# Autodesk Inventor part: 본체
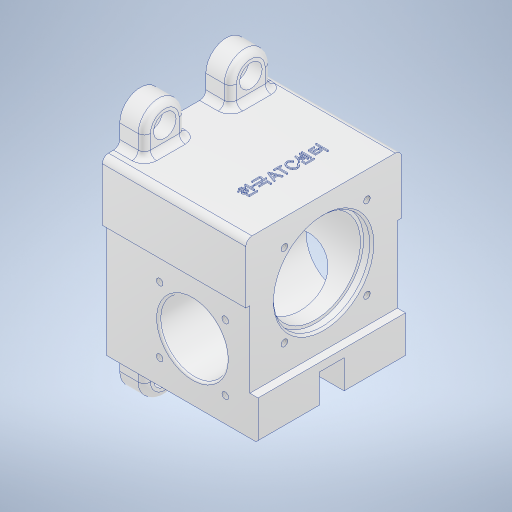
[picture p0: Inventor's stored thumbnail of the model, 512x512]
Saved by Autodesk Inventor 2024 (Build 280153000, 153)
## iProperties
Created: 2024-11
Part Number: 본체
Material: 알루미늄 6061
Document SubType Name: Modeling
Designer: user
Density: 2.7 g/cm^3
Appearance: 알루미늄 - 평지
Mass: 820.853 g
Surface Area: 546.228 cm^2
Volume: 304.02 cm^3
Author: user
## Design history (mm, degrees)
sketch "스케치1"
  geometry: L1 (-37, 0)-(37, 0); L2 (-37, 0)-(-37, 85); L3 (-37, 85)-(33, 85); L4 (33, 85)-(33, 19); L5 (33, 19)-(37, 19); L6 (37, 19)-(37, 0); L7 (-37, 56)-(33, 56); 2 further points
  constraints: 14 end point, 3 horizontal, 2 point on line, 1 coincident, 1 midpoint, 1 parallel, 1 perpendicular, 1 vertical
  dimensions: "d0" = 74 distance of L1.start L1.end; "d5" = 85 distance of L1.start L2.end; "d7" = 70 distance of L2.end L3.end; "d8" = 66 distance of L3.end L4.end; "d9" = 4 distance of L4.end L5.end; "d10" = 56 distance between parallel lines of L1 L7
extrude "돌출1" new body sketch "스케치1" stored distance "d11" = 72; taper "d12" = 0 deg
extrude "돌출2" join sketch "스케치1" stored distance "d13" = 76; taper "d14" = 0 deg
sketch "스케치2"
  geometry: L1 (-37, 56)-(-37, 0) reference; L2 (33, 85)-(-37, 85) reference; C1 r 16.5 at (5, 28); 1 further point
  constraints: 1 centre point
  dimensions: "d15" = 33 diameter of C1; "d16" = 57 distance from line of L2 C1.centre; "d17" = 42 distance from line of C1.centre L1
extrude "돌출3" cut sketch "스케치2" distance "d18" = 76; taper "d19" = 0 deg
fillet "모깎기1" dims "d20" = 1
sketch "스케치3"
  geometry: C1 r 17.5 at (5, 28) reference; 5 further points
  constraints: 2 horizontal alignment, 2 vertical alignment
  dimensions: "d21" = 32 distance of point (21, 12) point (-11, 12); "d22" = 16 horizontal distance of C1.centre point (21, 12); "d23" = 32 distance of point (-11, 12) point (-11, 44); "d24" = 16 horizontal distance of C1.centre point (-11, 12)
hole "구멍1" sketch "스케치3" at (-11, 44), (21, 44), (21, 12), (-11, 12) diameter "d25" = 3.242; stored, may be unused: countersink angle "d29" = 90 deg, drill point angle "d31" = 118 deg; dims "d26" = 8, "d27" = 4, "d28" = 2, "d30" = 10
sketch "스케치4"
  geometry: L1 (0, 0)-(72, 0) reference; L2 (30, 15)-(42, 15); L3 (42, 15)-(42, 0); L4 (42, 0)-(30, 0); L5 (30, 0)-(30, 15); 3 further points
  constraints: 8 end point, 2 midpoint, 2 parallel, 1 horizontal, 1 perpendicular, 1 point on line
  dimensions: "d32" = 12 distance of L3.end L4.end; "d33" = 15 distance of L2.end L3.end
extrude "돌출4" cut sketch "스케치4" extent not by distance; stored distance "d34" = 0; taper "d35" = 0 deg
sketch "스케치5"
  geometry: L1 (-30, 0)-(0, 0) reference; L2 (2, 85)-(-74, 85) reference; L3 (-72, 0)-(-42, 0) reference; L4 (-68.5, 95)-(-68.5, 85); L5 (-48.5, 95)-(-48.5, 85); L6 (-6.5, 95)-(-6.5, 85); L7 (-26.5, 95)-(-26.5, 85); L8 (-68.5, -10)-(-68.5, 0); L9 (-48.5, -10)-(-48.5, 0); L10 (-26.5, -10)-(-26.5, 0); L11 (-6.5, -10)-(-6.5, 0); A1 r 10 centre (-58.5, 95) between (-48.5, 95) and (-68.5, 95); A2 r 10 centre (-16.5, 95) between (-6.5, 95) and (-26.5, 95); A3 r 10 centre (-58.5, -10) between (-68.5, -10) and (-48.5, -10); A4 r 10 centre (-16.5, -10) between (-26.5, -10) and (-6.5, -10); 3 further points
  constraints: 16 end point, 10 point on circle, 8 point on line, 6 perpendicular, 4 centre point, 4 tangent, 1 parallel, 1 vertical
  dimensions: "d37" = 20 diameter of A1; "d38" = 10 vertical distance of A1.centre L2.end; "d39" = 20 diameter of A2; "d40" = 10 distance from line of A2.centre L2; "d41" = 42 distance of A2.centre A1.centre; "d42" = 20 diameter of A3; "d43" = 20 diameter of A4; "d44" = 42 distance of A4.centre A3.centre; "d45" = 10 distance from line of A3.centre L3; "d46" = 10 distance from line of L1 A4.centre; "d47" = 125 distance of point (-58.5, -20) point (-58.5, 105); "d48" = 22 distance of L7.end L5.end; "d49" = 6.5 dimension on L2.end L4.end; "d50" = 7.5 dimension on L2.start L6.end; "d51" = 5.5 dimension on L3.start L8.end; "d52" = 22 distance of L10.end L9.end
extrude "돌출5" join sketch "스케치5" distance "d53" = 12; taper "d54" = 0 deg
sketch "스케치6"
  geometry: A1 r 10 centre (16.5, 95) between (26.5, 95) and (6.5, 95) reference; A2 r 10 centre (58.5, 95) between (68.5, 95) and (48.5, 95) reference; A3 r 10 centre (16.5, -10) between (6.5, -10) and (26.5, -10) reference; A4 r 10 centre (58.5, -10) between (48.5, -10) and (68.5, -10) reference; 5 further points
  constraints: 4 coincident
hole "구멍2" sketch "스케치6" at (16.5, 95), (58.5, 95), (58.5, -10), (16.5, -10) diameter "d55" = 6.6; stored, may be unused: countersink angle "d59" = 90 deg, drill point angle "d61" = 118 deg; dims "d56" = 8, "d57" = 11, "d58" = 6.6, "d60" = 6.6
sketch "스케치7"
  geometry: L1 (74, 66)-(-2, 66) reference; C1 r 23.5 at (36, 33); 2 further points
  constraints: 1 centre point, 1 midpoint, 1 vertical alignment
  dimensions: "d62" = 47 diameter of C1; "d63" = 33 distance of point (36, 66) C1.centre
extrude "돌출6" cut sketch "스케치7" distance "d64" = 4; taper "d65" = 0 deg
sketch "스케치8"
  geometry: C1 r 23.5 at (0, 0) reference; C2 r 22 at (0, 0); 1 further point
  constraints: 1 centre point, 1 coincident
  dimensions: "d66" = 44 diameter of C2
extrude "돌출7" cut sketch "스케치8" distance "d67" = 48; taper "d68" = 0 deg
sketch "스케치9"
  geometry: C1 r 22 at (0, 0) reference; C2 r 17.5 at (0, 0); 1 further point
  constraints: 1 centre point, 1 coincident
  dimensions: "d69" = 35 diameter of C2
extrude "돌출8" cut sketch "스케치9" distance "d70" = 11; taper "d71" = 0 deg
sketch "스케치10"
  geometry: C1 r 17.5 at (0, 0) reference; C2 r 15 at (0, 0); 1 further point
  constraints: 1 centre point, 1 coincident
  dimensions: "d72" = 30 diameter of C2
extrude "돌출9" join sketch "스케치10" distance "d73" = 3; taper "d74" = 0 deg
chamfer "모따기1" distance "d75" = 1; stored, may be unused: second distance "d76" = 2, angle "d77" = 45 deg
fillet "모깎기2" dims "d78" = 0.6
fillet "모깎기3" dims "d79" = 3
sketch "스케치11"
  geometry: L1 (8.5, 33)-(65.5, 33); L2 (16.847, 53.153)-(57.153, 12.847); L3 (16.847, 12.847)-(57.153, 53.153); C1 r 15 at (37, 33) reference; A1 r 28.5 centre (37, 33) between (57.153, 53.153) and (57.153, 12.847); 3 further points
  constraints: 6 end point, 6 point on circle, 4 midpoint, 1 centre point, 1 coincident, 1 horizontal, 1 horizontal alignment
  dimensions: "d80" = 57 diameter of A1; "d81" = 45 deg angle of L1 L2; "d82" = 45 deg angle of L1 L3
hole "구멍3" sketch "스케치11" at (57.153, 53.153), (57.153, 12.847), (16.847, 12.847), (16.847, 53.153) diameter "d83" = 3.242; stored, may be unused: countersink angle "d87" = 90 deg, drill point angle "d89" = 118 deg; dims "d84" = 8, "d85" = 11, "d86" = 6.6, "d88" = 10
sketch "스케치13"
  geometry: L1 (70, 76)-(70, 0) reference; 2 further points
  constraints: 1 horizontal alignment, 1 other
  dimensions: "d93" = 20 distance from line of L1 point (50, 38)
feature "엠보싱2" sketch "스케치13" dims "d0" = 74, "d5" = 85, "d7" = 70, "d8" = 66, "d9" = 4, "d10" = 56, "d94" = 0.5, "d95" = 0
fillet "모깎기4" dims "d96" = 3
fillet "모깎기5" dims "d97" = 3
chamfer "모따기2" distance "d98" = 1; stored, may be unused: second distance "d99" = 2, angle "d100" = 45 deg
chamfer "모따기3" distance "d101" = 1; stored, may be unused: second distance "d102" = 2, angle "d103" = 45 deg
sketch "스케치14"
  geometry: L1 (74, 12)-(74, 0) reference; 4 further points
  constraints: 2 horizontal alignment, 1 midpoint
  dimensions: "d104" = 12 distance of point (62, 6) point (74, 6); "d105" = 40 distance of point (22, 6) point (62, 6)
hole "구멍4" sketch "스케치14" at (62, 6), (22, 6) diameter "d106" = 3.242; stored, may be unused: countersink angle "d110" = 90 deg, drill point angle "d112" = 118 deg; dims "d107" = 8, "d108" = 4, "d109" = 2, "d111" = 10
sketch "스케치15"
  geometry: 1 further point
sketch "스케치16"
  geometry: 1 further point
sketch "스케치17"
  geometry: C1 r 16.9 at (0, 0) reference; C2 r 15 at (0, 0); 1 further point
  constraints: 1 centre point, 1 coincident
  dimensions: "d113" = 30 diameter of C2
extrude "돌출10" cut sketch "스케치17" distance "d114" = 3; taper "d115" = 0 deg
fillet "모깎기6" dims "d116" = 3
node "솔리드1"
mirror "미러1"
node "작업 평면1"
feature "A9D066F2-1C7D-4E18-AEED-F7BC21143FA4" dims "d55" = 6.6, "d56" = 8, "d57" = 11, "d58" = 6.6, "d59" = 90 deg, "d60" = 6.6, "d61" = 118 deg
